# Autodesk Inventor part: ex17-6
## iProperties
Shininess: 64.0
Length Units: 11272
Angle Units: 11279
Time Units: 11290
Mass Units: 11286
Length Display Precision: 3
Angle Display Precision: 2
Compacted: True
Created: 2002-04
Part Number: ex17-6
Description: EXT CLIP, AXIAL, ROTOR CLIP
Document SubType Name: Modeling
Standard: EXT CLIP, AXIAL, ROTOR CLIP - SH-12
Designer: E. MOSS
Project: EVERGREEN VALLEY COLLEGE
Authority: MS. TEACHER
Density: 0.0
Volumn: 0.0
Area: 0.0
PropertySet Name: Model Information
Control State: 0
Master: False
Checked Out: False
Standard: ANSI
Type: CLIP-SH
Size: SH-12
Author: www
Revision Number: A
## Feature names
1. Extrusion1
